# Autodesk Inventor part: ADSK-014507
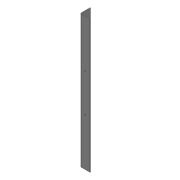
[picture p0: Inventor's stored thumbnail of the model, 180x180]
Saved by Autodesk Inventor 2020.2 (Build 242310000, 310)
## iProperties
Created: 2019-10
Part Number: ADSK-014507
Material: 1.0312 DC05
Document SubType Name: Blech
Designer: lutzd
Mass: 212.039 g
Surface Area: 1462.9 cm^2
Volume: 212.039 cm^3
Density: 1 g/cm^3
Sheet Metal Rule: Stahlblech 1.0312 - DC05 -   3.0 mm
Appearance: Stahl
Flat Pattern Width: 10.0786 cm
Flat Pattern Length: 70 cm
Flat Pattern Area: 705.501 cm^2
Sheet Metal Width: 100,786 mm
Sheet Metal Length: 700,000 mm
Sheet Metal Area: 70550,088 mm^2
VLDS_Profile: Default Part
VLDS_TimeStamp: 2016-07-29
VLDS_FailCnt: 0
VLDS_AcceptCnt: 0
Dimensions: 53x700x53 mm
Semi finished: Stahlblech 1.0312 - DC05 -   3.0 mm
Mass: 0,212 kg
DocNumber: ADSK-014507
Folder: 01 - Themengebiete\Simplification\01 - Packaging machine\Parts\
Original: C:\AB_Vault\CAD\01 - Themengebiete\Simplification\01 - Packaging machine\Parts\ADSK-014366.ipt
VDS_Category: 3D Komponenten
VDS_NumSchm: Autodesk
G_L: 100,8x700 mm
Thickness: 3,000 mm
VLT_Material: 1.0312 DC05
Title: rail
Author: lutzd
Revision Number: -
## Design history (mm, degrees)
node "Konturlasche1"
  sketch "Skizze1"
    geometry: L1 (0, 0)-(0, 50); L2 (0, 0)-(50, 0)
    constraints: 4 end point, 1 horizontal, 1 vertical
    dimensions: "d0" = 50 distance of L1.start L2.end; "d1" = 50 distance of L1.start L1.end
sketch "Skizze2"
  geometry: L1 (0, 700)-(0, 0) reference; L2 (-25, 451.5)-(-25, 248.5); 3 further points
  constraints: 2 end point, 1 coincident, 1 horizontal alignment, 1 midpoint, 1 vertical, 1 vertical alignment
  dimensions: "d43" = 25 distance between parallel lines of L1 L2; "d44" = 203 distance of L2.start L2.end
hole "Bohrung1" sketch "Skizze2" at (-25, 451.5), (-25, 248.5) diameter "d15" = 6.6; stored, may be unused: countersink angle "d19" = 90 deg, drill point angle "d21" = 118 deg; dims "d16" = 16, "d17" = 12.6, "d18" = 2, "d20" = 3 (= Stärke)
node "Volumenkörper1"
feature "Grobblech1" dims "d2" = 3 (= Stärke), "d3" = 3 (= BreiteBiegungsfreistellung), "d4" = 1.5 (= TiefeBiegungsfreistellung), "d5" = 6 (= MinimalRest), "d6" = 3 (= Übergangsradius), "d7" = 700, "d8" = 3 (= Biegeradius), "d9" = 3, "d10" = 12 (= GrößeEckenfreistellung), "d11" = 3 (= Abstandsgröße), "d12" = 3 (= JacobiRadiusGröße), "AbstandVerbindung" = 0.01
feature "Biegung1" dims "d2" = 3 (= Stärke), "d3" = 3 (= BreiteBiegungsfreistellung), "d4" = 1.5 (= TiefeBiegungsfreistellung), "d5" = 6 (= MinimalRest), "d6" = 3 (= Übergangsradius), "d8" = 3 (= Biegeradius), "d9" = 3, "AbstandVerbindung" = 0.01
feature "Ecke1" dims "d9" = 3, "d10" = 12 (= GrößeEckenfreistellung), "d11" = 3 (= Abstandsgröße), "d12" = 3 (= JacobiRadiusGröße)
feature "Definition1"
other parameters: "Stärke" = 3 (derived), "KFaktor" = 4.4, "Biegeradius" = 3 (= Stärke), "BreiteBiegungsfreistellung" = 3 (= Stärke), "TiefeBiegungsfreistellung" = 1.5 (= 0.5 x Stärke), "GrößeEckenfreistellung" = 12 (= 4 x Stärke), "MinimalRest" = 6 (= 2 x Stärke), "Übergangsradius" = 3 (= Biegeradius), "JacobiRadiusGröße" = 3 (= Biegeradius), "Abstandsgröße" = 3 (= Stärke), "Abstandsgröße" = 3, "Biegeradius" = 3, "BreiteBiegungsfreistellung" = 3, "GrößeEckenfreistellung" = 12, "JacobiRadiusGröße" = 3, "MinimalRest" = 6, "Stärke" = 3, "TiefeBiegungsfreistellung" = 1.5, "Übergangsradius" = 3
